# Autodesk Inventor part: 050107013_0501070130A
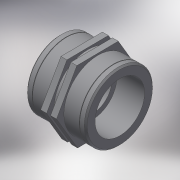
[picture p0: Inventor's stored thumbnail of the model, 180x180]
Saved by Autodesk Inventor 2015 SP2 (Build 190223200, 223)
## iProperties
Created: 2017-05
Part Number: 050107013_0501070130A
Material: Generic
Description: PLASSON SOCKET PP 1.1/4"-1.1/4"
Document SubType Name: Modeling
Designer: KIM
Density: 1 g/cm^3
Appearance: Default
Author: KIM
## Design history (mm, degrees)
derived "050107.ipt"
feature "Solid1::050107.ipt"
tag "TaggingFeature1"
body "Solid1"
other parameters: "d0" = 54, "d2" = 38.952, "d3" = 25, "d6" = 57, "d7" = 31.1616, "d14" = 0, "d15" = 1.16856, "d18" = 5.4, "d19" = 1.8, "d20" = 0.5, "d21" = 0.5, "d22" = 57, "Rp_" = 38.952, "H_" = 54, "l_2" = 25
